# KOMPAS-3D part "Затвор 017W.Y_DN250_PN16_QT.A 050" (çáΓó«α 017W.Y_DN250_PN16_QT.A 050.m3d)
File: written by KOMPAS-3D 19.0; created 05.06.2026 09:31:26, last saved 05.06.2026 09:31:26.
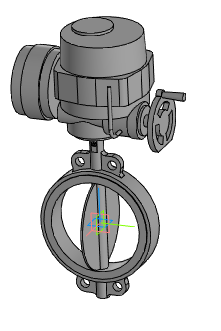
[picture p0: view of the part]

Document properties: Автор: Энергия; Полное имя файла: ..\..\..\3d для проектировщиков\x.x Тип 017W.Y(S) Затвор дисковый поворотный межфланцевый\Затвор 017W.Y(S)_DN32-DN1200_QT.A_MT903.A\Затвор 017W.Y_DN250_PN16_QT.A 050.a3d

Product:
- Part/product: Затвор 017W.Y_DN250_PN16_QT.A 050
    Масса: 133.275

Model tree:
1. Операция без истории:1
